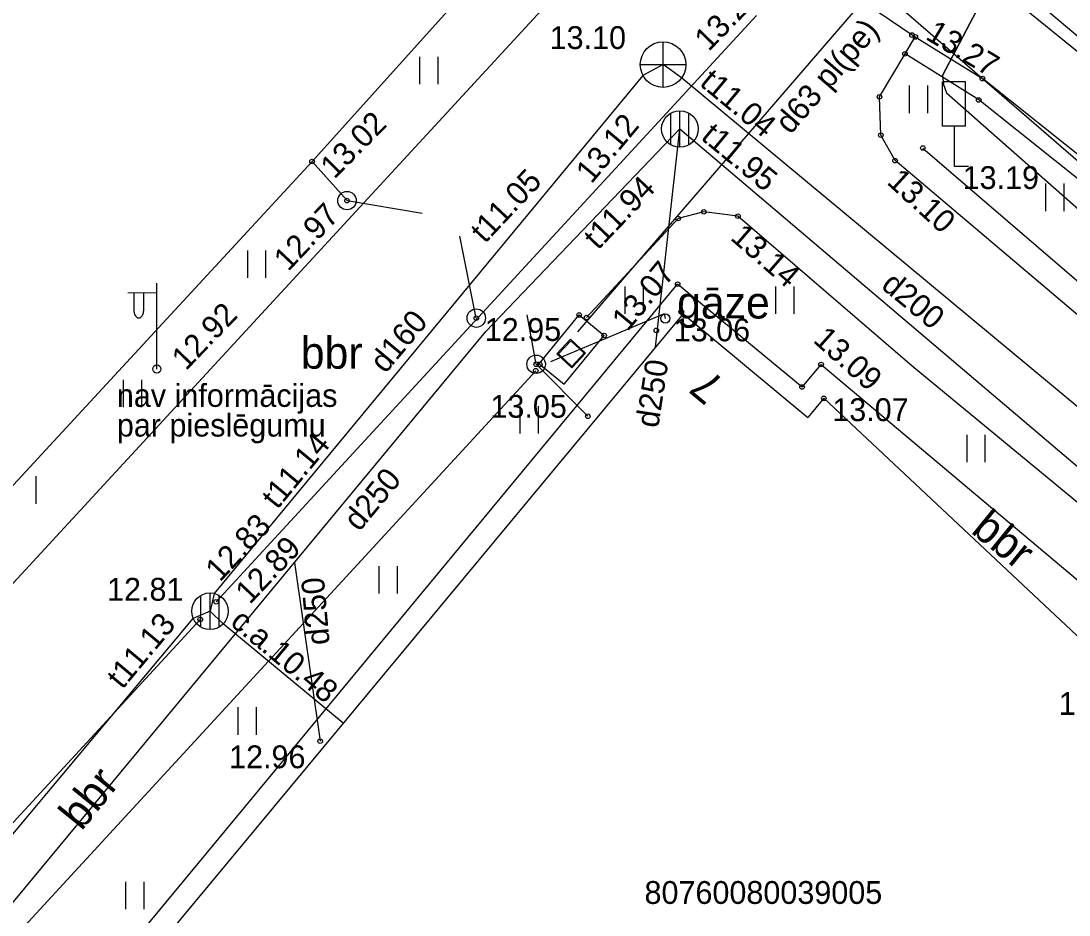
# Model space of a CAD drawing. Extents: x 503877 to 504025, y 304562 to 304725.
# Drawn here: x 503910.05 to 503933, y 304599.07 to 304618.66 of the extents above; entities that cross this region are included whole.
import ezdxf

# ---------------------------------------------------------------- set-up
doc = ezdxf.new("R2010")
doc.units = 0
for name, color, linetype in [('25', 7, 'Continuous'), ('41', 7, 'Continuous'), ('APGS_ACRL_####_####_#', 7, 'Continuous'), ('APGS_ELEM_####_####_#', 7, 'Continuous'), ('APGS_ELEM_####_TKST_#', 7, 'Continuous'), ('APGS_VADP_ZSPR_####_#', 7, 'Continuous'), ('BUVE_BDET_####_####_#', 7, 'Continuous'), ('BUVE_EKAS_####_####_#', 7, 'Continuous'), ('BUVE_EKAS_ADRS_TKST_#', 7, 'Continuous'), ('CELI_CAPM_####_####_#', 7, 'Continuous'), ('CELI_CMAL_####_####_#', 7, 'Continuous'), ('CELI_CSEG_####_TKST_#', 7, 'Continuous'), ('CELI_ELEM_####_####_#', 7, 'Continuous'), ('CELI_SEGL_####_####_#', 7, 'Continuous'), ('CELI_TAKA_####_####_#', 7, 'Continuous'), ('GAZE_ELEM_####_####_#', 7, 'Continuous'), ('GAZE_VADP_VSP2_####_#', 7, 'Continuous'), ('GAZE_VADP_ZSPD_####_#', 7, 'Continuous'), ('GAZE_VADP_ZSPD_TKST_#', 7, 'Continuous'), ('LKAN_ELEM_####_####_#', 7, 'Continuous'), ('LKAN_ELEM_PAST_TKST_#', 7, 'Continuous'), ('LKAN_VADP_PAST_####_#', 7, 'Continuous'), ('LKAN_VADP_PAST_TKST_#', 7, 'Continuous'), ('NORB_ELEM_####_####_#', 7, 'Continuous'), ('NORB_ZOGS_BARJ_####_#', 7, 'Continuous'), ('NORB_ZOGS_ZSTP_####_#', 7, 'Continuous'), ('RELJ_AATZ_####_TKST_#', 7, 'Continuous'), ('RELJ_ELEM_####_####_#', 7, 'Continuous'), ('SKAN_ELEM_####_####_#', 7, 'Continuous'), ('SKAN_ELEM_PAST_TKST_#', 7, 'Continuous'), ('SKAN_VADP_PAST_####_#', 7, 'Continuous'), ('SKAN_VADP_PAST_####_I', 7, 'Continuous'), ('SKAN_VADP_PAST_TKST_#', 7, 'Continuous'), ('TERT_ELEM_####_####_#', 7, 'Continuous'), ('TERT_KRND_####_####_#', 7, 'Continuous'), ('UDTK_ELEM_####_TKST_#', 7, 'Continuous')]:
    doc.layers.add(name, color=color, linetype=linetype)

msp = doc.modelspace()

# ---------------------------------------------------------------- linework, layer by layer
at = {"layer": '25'}
msp.add_line((503924.947, 304625.297), (503985.325, 304574.255), dxfattribs=at)
at = {"layer": 'APGS_ACRL_####_####_#'}
msp.add_line((503930.237, 304617.463), (503934.246, 304625.165), dxfattribs=at)
at = {"layer": 'APGS_ELEM_####_####_#'}
for p, q in [((503913.028, 304611.035), (503913.028, 304612.918)), ((503913.028, 304612.702), (503912.393, 304612.697)), ((503912.528, 304612.698), (503912.528, 304612.306)), ((503912.738, 304612.7), (503912.738, 304612.306))]:
    msp.add_line(p, q, dxfattribs=at)
msp.add_circle((503913.028, 304611.035), 0.09, dxfattribs=at)
msp.add_ellipse((503912.633, 304612.306), major_axis=(0, 0.151), ratio=0.695971, start_param=1.570796, end_param=4.712389, dxfattribs=at)
at = {"layer": 'APGS_VADP_ZSPR_####_#'}
for p, q in [((503939.108, 304634.506), (503930.237, 304617.463)), ((503930.237, 304617.463), (503930.255, 304617.266)), ((503930.255, 304617.266), (503930.322, 304617.086)), ((503930.322, 304617.086), (503944.336, 304604.708))]:
    msp.add_line(p, q, dxfattribs=at)
at = {"layer": 'BUVE_BDET_####_####_#'}
for p, q in [((503921.398, 304611.15), (503922.277, 304612.219)), ((503922.277, 304612.219), (503922.824, 304611.769)), ((503921.945, 304610.7), (503922.824, 304611.769)), ((503921.398, 304611.15), (503921.945, 304610.7))]:
    msp.add_line(p, q, dxfattribs=at)
at = {"layer": 'BUVE_EKAS_####_####_#'}
for p, q in [((503924.556, 304612.247), (503901.224, 304584.141)), ((503924.556, 304612.247), (503927.286, 304609.975)), ((503927.634, 304610.394), (503927.286, 304609.975)), ((503927.634, 304610.394), (503934.287, 304604.153))]:
    msp.add_line(p, q, dxfattribs=at)
at = {"layer": 'CELI_CAPM_####_####_#'}
for p, q in [((503923.377, 304620.99), (503883.259, 304577.462)), ((503914.328, 304605.935), (503926.162, 304618.779)), ((503900.43, 304590.851), (503913.979, 304605.548))]:
    msp.add_line(p, q, dxfattribs=at)
at = {"layer": 'CELI_CMAL_####_####_#'}
for p, q in [((503929.413, 304617.939), (503929.637, 304618.31)), ((503929.637, 304618.31), (503929.567, 304618.35)), ((503929.637, 304618.31), (503931.107, 304617.397)), ((503928.854, 304616.997), (503929.413, 304617.939)), ((503935.883, 304613.584), (503931.107, 304617.397)), ((503928.884, 304616.158), (503928.854, 304616.997)), ((503929.195, 304615.6), (503928.884, 304616.158)), ((503941.74, 304604.987), (503929.195, 304615.6)), ((503925.006, 304614.477), (503924.443, 304614.332)), ((503925.754, 304614.383), (503925.006, 304614.477)), ((503929.569, 304611.095), (503925.754, 304614.383)), ((503924.443, 304614.332), (503922.441, 304612.163)), ((503912.215, 304598.126), (503924.433, 304612.895)), ((503927.158, 304610.641), (503924.433, 304612.895)), ((503921.326, 304610.998), (503899.68, 304587.482)), ((503927.158, 304610.641), (503927.574, 304611.135)), ((503927.574, 304611.135), (503934.968, 304604.913)), ((503934.355, 304607.151), (503929.569, 304611.095))]:
    msp.add_line(p, q, dxfattribs=at)
at = {"layer": 'CELI_ELEM_####_####_#'}
for p, q in [((503930.734, 304617.325), (503930.234, 304617.325)), ((503930.234, 304616.356), (503930.234, 304617.325)), ((503930.734, 304616.356), (503930.734, 304617.325)), ((503930.734, 304616.356), (503930.234, 304616.356)), ((503930.488, 304616.356), (503930.488, 304615.478)), ((503930.488, 304615.478), (503930.803, 304615.478))]:
    msp.add_line(p, q, dxfattribs=at)
at = {"layer": 'CELI_SEGL_####_####_#'}
msp.add_line((503929.567, 304618.35), (503925.739, 304620.956), dxfattribs=at)
at = {"layer": 'CELI_TAKA_####_####_#'}
for p, q in [((503931.027, 304616.929), (503929.413, 304617.939)), ((503935.489, 304613.368), (503931.027, 304616.929))]:
    msp.add_line(p, q, dxfattribs=at)
at = {"layer": 'GAZE_ELEM_####_####_#'}
for points in [[(503922.119, 304611.061), (503921.791, 304611.365), (503922.09, 304611.688), (503922.418, 304611.384)], [(503922.118, 304611.093), (503921.824, 304611.366), (503922.092, 304611.655), (503922.386, 304611.382)]]:
    msp.add_lwpolyline(points, close=True, dxfattribs=at)
msp.add_circle((503924.162, 304612.142), 0.1, dxfattribs=at)
at = {"layer": 'GAZE_VADP_VSP2_####_#'}
for p, q in [((503928.77, 304619.428), (503923.221, 304612.989)), ((503928.77, 304619.428), (503933.852, 304615.028)), ((503923.221, 304612.989), (503922.241, 304611.853))]:
    msp.add_line(p, q, dxfattribs=at)
at = {"layer": 'GAZE_VADP_ZSPD_####_#'}
for p, q in [((503924.14, 304612.243), (503922.757, 304611.662)), ((503924.14, 304612.243), (503924.162, 304612.142)), ((503922.757, 304611.662), (503921.649, 304611.196))]:
    msp.add_line(p, q, dxfattribs=at)
at = {"layer": 'LKAN_ELEM_####_####_#'}
for p, q in [((503924.482, 304615.893), (503924.482, 304616.693)), ((503924.282, 304615.947), (503924.282, 304616.639)), ((503924.682, 304615.947), (503924.682, 304616.639)), ((503914.193, 304605.33), (503914.193, 304606.13)), ((503913.993, 304605.384), (503913.993, 304606.076)), ((503914.393, 304605.384), (503914.393, 304606.076))]:
    msp.add_line(p, q, dxfattribs=at)
for centre in [(503924.482, 304616.293), (503914.193, 304605.73)]:
    msp.add_circle(centre, 0.4, dxfattribs=at)
at = {"layer": 'LKAN_VADP_PAST_####_#'}
for p, q in [((503920.234, 304611.854), (503924.482, 304616.293)), ((503923.945, 304611.511), (503924.482, 304616.293)), ((503924.482, 304616.293), (503942.453, 304601.026)), ((503900.852, 304588.457), (503920.234, 304611.854)), ((503916.042, 304606.794), (503916.606, 304602.884)), ((503914.285, 304606.119), (503914.193, 304605.73)), ((503914.193, 304605.73), (503913.827, 304605.568)), ((503914.193, 304605.73), (503914.481, 304605.453))]:
    msp.add_line(p, q, dxfattribs=at)
at = {"layer": 'NORB_ELEM_####_####_#'}
for centre in [(503917.193, 304614.724), (503920.024, 304612.15), (503921.335, 304611.14)]:
    msp.add_circle(centre, 0.202, dxfattribs=at)
at = {"layer": 'NORB_ZOGS_BARJ_####_#'}
for p, q in [((503917.193, 304614.724), (503918.839, 304614.449)), ((503920.024, 304612.15), (503919.667, 304613.944)), ((503921.335, 304611.14), (503921.139, 304612.224))]:
    msp.add_line(p, q, dxfattribs=at)
at = {"layer": 'NORB_ZOGS_ZSTP_####_#'}
for p, q in [((503916.428, 304615.582), (503922.264, 304622.078)), ((503882.208, 304578.545), (503916.428, 304615.582)), ((503916.428, 304615.582), (503917.193, 304614.724)), ((503922.468, 304610.001), (503921.335, 304611.14))]:
    msp.add_line(p, q, dxfattribs=at)
at = {"layer": 'RELJ_ELEM_####_####_#'}
for centre in [(503929.567, 304618.35), (503929.637, 304618.31), (503929.413, 304617.939), (503931.107, 304617.397), (503928.854, 304616.997), (503931.027, 304616.929), (503928.884, 304616.158), (503929.802, 304615.876), (503916.428, 304615.582), (503929.195, 304615.6), (503917.193, 304614.724), (503924.443, 304614.332), (503925.006, 304614.477), (503925.754, 304614.383), (503924.433, 304612.895), (503924.513, 304612.29), (503920.024, 304612.15), (503922.277, 304612.219), (503922.441, 304612.163), (503923.967, 304611.881), (503922.824, 304611.769), (503921.335, 304611.14), (503921.415, 304611.136), (503927.574, 304611.135), (503921.326, 304610.998), (503927.158, 304610.641), (503927.634, 304610.394), (503922.468, 304610.001), (503914.328, 304605.935), (503913.979, 304605.548), (503916.606, 304602.884)]:
    msp.add_circle(centre, 0.05, dxfattribs=at)
at = {"layer": 'SKAN_ELEM_####_####_#'}
for p, q in [((503924.114, 304617.203), (503924.114, 304618.203)), ((503923.614, 304617.703), (503924.614, 304617.703))]:
    msp.add_line(p, q, dxfattribs=at)
msp.add_circle((503924.114, 304617.703), 0.5, dxfattribs=at)
at = {"layer": 'SKAN_VADP_PAST_####_#'}
for p, q in [((503924.114, 304617.703), (503923.673, 304617.468)), ((503924.52, 304617.411), (503924.114, 304617.703)), ((503923.673, 304617.468), (503919.569, 304612.506)), ((503938.11, 304606.113), (503924.52, 304617.411)), ((503919.569, 304612.506), (503914.285, 304606.119)), ((503895.56, 304583.751), (503913.827, 304605.568)), ((503917.109, 304603.276), (503914.481, 304605.453))]:
    msp.add_line(p, q, dxfattribs=at)
at = {"layer": 'SKAN_VADP_PAST_####_I'}
msp.add_line((503945.224, 304608.195), (503926.692, 304623.27), dxfattribs=at)
at = {"layer": 'TERT_ELEM_####_####_#'}
for p, q in [((503918.787, 304617.272), (503918.787, 304617.872)), ((503919.187, 304617.272), (503919.187, 304617.872)), ((503929.514, 304616.643), (503929.514, 304617.243)), ((503929.914, 304616.643), (503929.914, 304617.243)), ((503932.496, 304614.496), (503932.496, 304615.096)), ((503932.896, 304614.496), (503932.896, 304615.096)), ((503915.019, 304613.029), (503915.019, 304613.629)), ((503915.419, 304613.029), (503915.419, 304613.629)), ((503923.287, 304612.244), (503923.287, 304612.844)), ((503923.687, 304612.244), (503923.687, 304612.844)), ((503926.583, 304612.244), (503926.583, 304612.844)), ((503926.983, 304612.244), (503926.983, 304612.844)), ((503912.298, 304610.201), (503912.298, 304610.801)), ((503912.698, 304610.201), (503912.698, 304610.801)), ((503920.984, 304609.625), (503920.984, 304610.225)), ((503921.384, 304609.625), (503921.384, 304610.225)), ((503930.77, 304608.997), (503930.77, 304609.597)), ((503931.17, 304608.997), (503931.17, 304609.597)), ((503910.383, 304608.085), (503910.383, 304608.685)), ((503917.897, 304606.116), (503917.897, 304606.716)), ((503918.297, 304606.116), (503918.297, 304606.716)), ((503914.81, 304603.026), (503914.81, 304603.626)), ((503915.21, 304603.026), (503915.21, 304603.626)), ((503912.35, 304599.203), (503912.35, 304599.803)), ((503912.75, 304599.203), (503912.75, 304599.803))]:
    msp.add_line(p, q, dxfattribs=at)
at = {"layer": 'TERT_KRND_####_####_#'}
msp.add_line((503929.802, 304615.876), (503940.453, 304606.703), dxfattribs=at)

# ---------------------------------------------------------------- texts
at = {"layer": '41'}
msp.add_text('80760080039005', height=0.5, dxfattribs=at).set_placement((503923.708, 304599.319))
at = {"layer": 'APGS_ELEM_####_TKST_#'}
for s, p in [('nav informācijas', (503912.153, 304610.206)), ('par pieslēgumu', (503912.153, 304609.556))]:
    msp.add_text(s, height=0.5, dxfattribs=at).set_placement(p)
at = {"layer": 'BUVE_EKAS_ADRS_TKST_#'}
msp.add_text('7', height=0.7, rotation=140.2493, dxfattribs=at).set_placement((503925.497, 304610.752))
at = {"layer": 'CELI_CSEG_####_TKST_#'}
msp.add_text('bbr', height=0.7, dxfattribs=at).set_placement((503916.181, 304611.042))
for rotation, p in [(320.9243, (503930.832, 304607.463)), (50.9613, (503911.377, 304600.9))]:
    msp.add_text('bbr', height=0.7, rotation=rotation, dxfattribs=at).set_placement(p)
at = {"layer": 'GAZE_ELEM_####_####_#'}
msp.add_text(' gāze', height=0.7, dxfattribs=at).set_placement((503924.162, 304612.142))
at = {"layer": 'GAZE_VADP_ZSPD_TKST_#'}
msp.add_text('d63 pl(pe)', height=0.5, rotation=49.2421, dxfattribs=at).set_placement((503926.903, 304616.155))
at = {"layer": 'LKAN_ELEM_PAST_TKST_#'}
msp.add_text(' 13.12', height=0.5, rotation=50.1582, dxfattribs=at).set_placement((503922.426, 304614.932))
msp.add_text(' 12.81', height=0.5, dxfattribs=at).set_placement((503911.752, 304605.96))
at = {"layer": 'LKAN_VADP_PAST_TKST_#'}
for s, rotation, p in [('t11.95', 320.3604, (503924.919, 304616.083)), ('t11.94', 46.2123, (503922.689, 304613.625)), ('d200', 320.3604, (503928.865, 304612.823)), ('d250', 81.2546, (503924.007, 304609.73)), ('d250', 50.3604, (503917.459, 304607.456)), ('d250', 95.0682, (503916.816, 304605.01))]:
    msp.add_text(s, height=0.5, rotation=rotation, dxfattribs=at).set_placement(p)
at = {"layer": 'RELJ_AATZ_####_TKST_#'}
for s, rotation, p in [(' 13.23', 45.7323, (503924.983, 304617.842)), (' 13.27', 329.0752, (503929.678, 304618.371)), (' 13.02', 45.3505, (503916.787, 304615.049)), (' 13.10', 317.5188, (503928.857, 304615.231)), (' 12.97', 46.5378, (503915.778, 304613.022)), (' 13.14', 319.0786, (503925.426, 304614.005)), (' 13.07', 50.2412, (503923.216, 304611.698)), (' 12.92', 46.0721, (503913.537, 304610.851)), (' 13.09', 318.1636, (503927.24, 304611.765)), (' 12.83', 46.6581, (503914.282, 304606.219)), (' 12.89', 46.5409, (503914.936, 304605.727))]:
    msp.add_text(s, height=0.5, rotation=rotation, dxfattribs=at).set_placement(p)
for s, p in [(' 13.19', (503930.488, 304614.978)), (' 12.95', (503920.024, 304611.65)), (' 13.06', (503924.162, 304611.642)), (' 13.05', (503920.148, 304609.968)), (' 13.07', (503927.634, 304609.894)), (' 12.96', (503914.425, 304602.291))]:
    msp.add_text(s, height=0.5, dxfattribs=at).set_placement(p)
at = {"layer": 'SKAN_ELEM_PAST_TKST_#'}
msp.add_text(' 13.10', height=0.5, dxfattribs=at).set_placement((503921.444, 304618.045))
at = {"layer": 'SKAN_VADP_PAST_TKST_#'}
for s, rotation, p in [('t11.04', 320.2635, (503924.891, 304617.265)), ('t11.05', 46.7357, (503920.213, 304613.768)), ('d160', 50.0604, (503918.033, 304610.918)), ('t11.14', 50.4026, (503915.666, 304607.943)), ('t11.13', 50.0604, (503912.273, 304604.001)), ('c.a.10.48', 320.3604, (503914.609, 304605.445))]:
    msp.add_text(s, height=0.5, rotation=rotation, dxfattribs=at).set_placement(p)
at = {"layer": 'UDTK_ELEM_####_TKST_#'}
msp.add_text(' 13.15', height=0.5, dxfattribs=at).set_placement((503932.593, 304603.458))

doc.saveas('drawing.dxf')
